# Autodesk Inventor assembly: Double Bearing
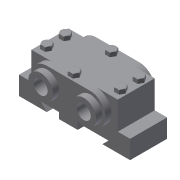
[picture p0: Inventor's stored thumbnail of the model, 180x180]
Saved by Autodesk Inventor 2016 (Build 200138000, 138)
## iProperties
Shininess: 64.0
Length Units: 11269
Angle Units: 11279
Time Units: 11290
Mass Units: 11283
Length Display Precision: 3
Angle Display Precision: 2
Created: 2002-02
Part Number: Double Bearing
Document SubType Name: Assembly
Designer: ***
Density: 0.0
Volumn: 0.0
Area: 0.0
PropertySet Name: Model Information
Control State: 0
Master: False
Checked Out: False
Author: ***
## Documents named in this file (5)
- C:\Autodesk Inventor 2016\c12\c12_tut02_inv\Double Bearing.iam
- C:\Autodesk Inventor 2016\c12\c12_tut02_inv\Base.ipt
- C:\Autodesk Inventor 2016\c12\c12_tut02_inv\Cap.ipt
- C:\Autodesk Inventor 2016\c12\c12_tut02_inv\Bushing.ipt
- C:\Autodesk Inventor 2016\c12\c12_tut02_inv\Bolt.ipt
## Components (10 placed, 4 different names)
1. Base:1 — Insert:1, Insert:2
2. Cap:1 — Insert:1, Insert:2, Insert:3, Insert:4, Insert:5, Insert:6
3. Bushing:1 — Insert:3
4. Bushing:2 — Insert:4
5. Bolt:1 — Insert:5
6. Bolt:6
7. Bolt:7
8. Bolt:8
9. Bolt:5 — Insert:6
10. Bolt:9
## Component patterns: Component Pattern 1 (4 elements), Component Pattern 2 (2 elements)
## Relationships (6: Insert 6)
- Insert:1: Base:1 ↔ Cap:1
- Insert:2: Base:1 ↔ Cap:1
- Insert:3: Cap:1 ↔ Bushing:1
- Insert:4: Cap:1 ↔ Bushing:2
- Insert:5: Cap:1 ↔ Bolt:1
- Insert:6: Cap:1 ↔ Bolt:5
